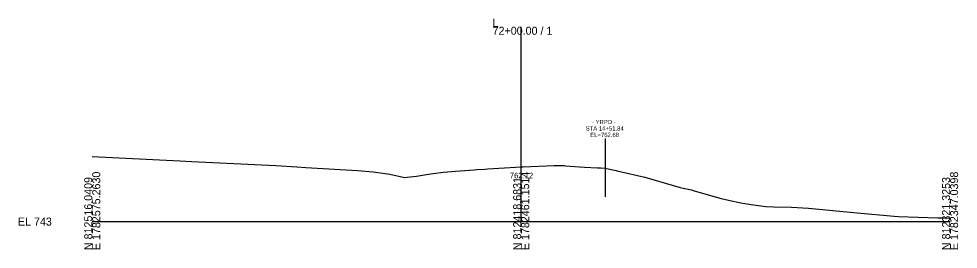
# Model space of a CAD drawing. Extents: x -26 to 7903, y -10 to 9573.
# Drawn here: x 3974.3 to 4302.8, y 2990.3 to 3071 of the extents above; entities that cross this region are included whole.
import ezdxf

# ---------------------------------------------------------------- set-up
doc = ezdxf.new("R2010")
doc.units = 0
for name, color, linetype in [('Exist Cross Section Cell', 7, 'Continuous'), ('Exist XS Center Line Elevation Label', 7, 'Continuous'), ('Exist XS Ground Line', 7, 'Continuous'), ('Prop XS Vertical Lines Alignments', 7, 'Continuous')]:
    doc.layers.add(name, color=color, linetype=linetype)

msp = doc.modelspace()

# ---------------------------------------------------------------- linework, layer by layer
at = {"layer": 'Exist Cross Section Cell'}
for p, q in [((4150, 3000), (4150, 3068.24)), ((4000, 3000), (4150, 3000)), ((4150, 3000), (4300, 3000))]:
    msp.add_line(p, q, dxfattribs=at)
at = {"layer": 'Exist XS Ground Line'}
for p, q in [((4000, 3022.75), (4030.62, 3021.31)), ((4030.62, 3021.31), (4034.77, 3021.08)), ((4034.77, 3021.08), (4064.19, 3019.62)), ((4064.19, 3019.62), (4071.52, 3019.12)), ((4150.7, 3019.16), (4161.58, 3019.62)), ((4161.58, 3019.62), (4165.05, 3019.58)), ((4165.05, 3019.58), (4165.54, 3019.57)), ((4165.54, 3019.57), (4170.39, 3019.21)), ((4071.52, 3019.12), (4074.74, 3018.92)), ((4074.74, 3018.92), (4092.71, 3017.84)), ((4092.71, 3017.84), (4098.19, 3017.41)), ((4098.19, 3017.41), (4103.2, 3016.71)), ((4103.2, 3016.71), (4104.06, 3016.58)), ((4104.06, 3016.58), (4104.53, 3016.48)), ((4104.53, 3016.48), (4109.31, 3015.45)), ((4110.18, 3015.56), (4113.35, 3015.96)), ((4113.35, 3015.96), (4116.9, 3016.45)), ((4116.9, 3016.45), (4119.23, 3016.79)), ((4119.23, 3016.79), (4122.88, 3017.33)), ((4122.88, 3017.33), (4126.98, 3017.63)), ((4126.98, 3017.63), (4133.57, 3018.15)), ((4133.57, 3018.15), (4134.51, 3018.22)), ((4134.51, 3018.22), (4137.13, 3018.39)), ((4137.13, 3018.39), (4138.29, 3018.47)), ((4138.29, 3018.47), (4150, 3019.12)), ((4150, 3019.12), (4150.7, 3019.16)), ((4170.39, 3019.21), (4172.12, 3019.1)), ((4172.12, 3019.1), (4176.71, 3018.85)), ((4176.71, 3018.85), (4177.82, 3018.77)), ((4177.82, 3018.77), (4179.25, 3018.71)), ((4179.25, 3018.71), (4183.26, 3017.85)), ((4183.26, 3017.85), (4183.58, 3017.78)), ((4183.58, 3017.78), (4184.08, 3017.67)), ((4184.08, 3017.67), (4193.3, 3015.6)), ((4109.31, 3015.45), (4110.18, 3015.56)), ((4193.3, 3015.6), (4203.61, 3012.48)), ((4203.61, 3012.48), (4205.63, 3011.97)), ((4205.63, 3011.97), (4206.71, 3011.72)), ((4206.71, 3011.72), (4209.54, 3011.08)), ((4209.54, 3011.08), (4210.54, 3010.76)), ((4210.54, 3010.76), (4219.95, 3008.12)), ((4219.95, 3008.12), (4222.56, 3007.49)), ((4222.56, 3007.49), (4226.79, 3006.61)), ((4226.79, 3006.61), (4230.48, 3005.95)), ((4230.48, 3005.95), (4235.51, 3005.31)), ((4235.51, 3005.31), (4238.2, 3005.11)), ((4238.2, 3005.11), (4244.51, 3005.01)), ((4244.51, 3005.01), (4250.53, 3004.64)), ((4250.53, 3004.64), (4267.52, 3003.09)), ((4267.52, 3003.09), (4280.4, 3001.87)), ((4280.4, 3001.87), (4281.9, 3001.79)), ((4281.9, 3001.79), (4295.71, 3001.28)), ((4295.71, 3001.28), (4297.61, 3001.26)), ((4297.61, 3001.26), (4300, 3001.16))]:
    msp.add_line(p, q, dxfattribs=at)
at = {"layer": 'Prop XS Vertical Lines Alignments'}
msp.add_line((4179.33, 3029.12), (4179.33, 3008.69), dxfattribs=at)

# ---------------------------------------------------------------- texts
at = {"layer": 'Exist Cross Section Cell'}
for s, p in [('L', (4140, 3068.24)), ('72+00.00 / 1', (4140, 3065.44)), ('EL 743', (3974, 2998.6))]:
    msp.add_text(s, height=2.8, dxfattribs=at).set_placement(p)
for s, p in [('E 1782575.2630', (4002.8, 2990)), ('E 1782461.1514', (4152.8, 2990)), ('E 1782347.0398', (4302.8, 2990)), ('N 812516.0409', (4000, 2990)), ('N 812418.6831', (4150, 2990)), ('N 812321.3253', (4300, 2990))]:
    msp.add_text(s, height=2.8, rotation=90, dxfattribs=at).set_placement(p)
at = {"layer": 'Exist XS Center Line Elevation Label'}
msp.add_text('762.12', height=2, dxfattribs=at).set_placement((4146.03, 3015.12))
at = {"layer": 'Prop XS Vertical Lines Alignments'}
for s, p in [('STA 14+51.84', (4172.56, 3031.87)), ('- YRPD -', (4174.75, 3034.12)), ('EL=762.68', (4174.15, 3029.62))]:
    msp.add_text(s, height=1.5, dxfattribs=at).set_placement(p)

doc.saveas('drawing.dxf')
